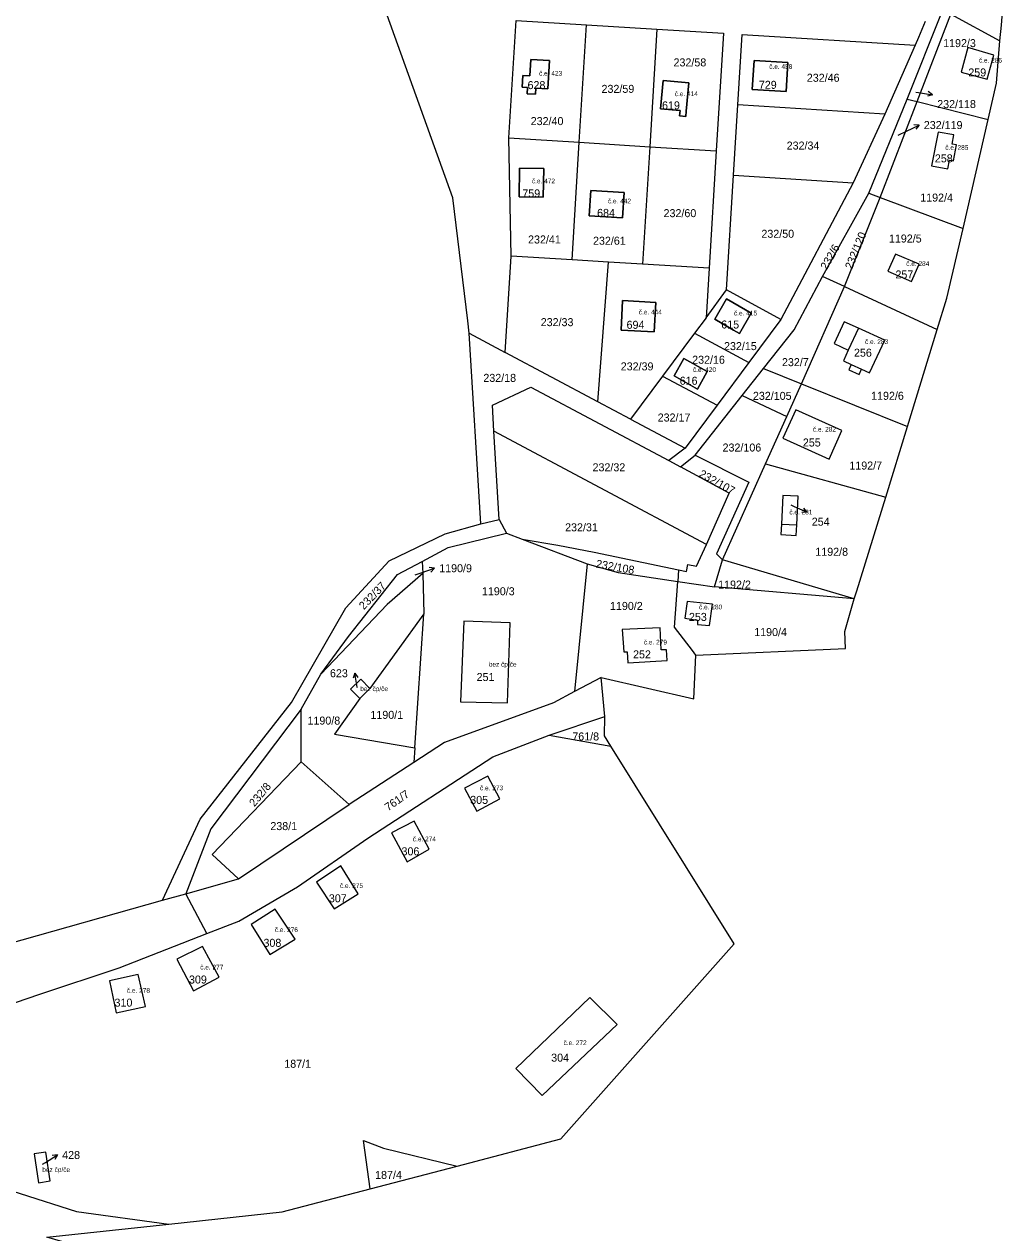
# Model space of a CAD drawing. Extents: x -887272 to -877616, y -1026687 to -1019819.
# Drawn here: x -882028.8 to -881820, y -1024011.9 to -1023755.1 of the extents above; entities that cross this region are included whole.
import ezdxf

# ---------------------------------------------------------------- set-up
doc = ezdxf.new("R2010")
doc.units = 0
for name, color, linetype in [('Definiční body', 7, 'Continuous'), ('Hranice parcel', 7, 'Continuous'), ('Parcelní čísla', 7, 'Continuous'), ('Polygon budovy', 7, 'Continuous'), ('Pop  PČ popisy', 7, 'Continuous'), ('Vnitřní kresba', 7, 'Continuous')]:
    doc.layers.add(name, color=color, linetype=linetype)

msp = doc.modelspace()

# ---------------------------------------------------------------- linework, layer by layer
at = {"layer": 'Hranice parcel'}
for p, q in [((-881841.17, -1023770.99), (-881833.85, -1023752.71)), ((-881839.01, -1023771.53), (-881831.92, -1023752.98)), ((-881831.92, -1023752.98), (-881821.47, -1023758.6)), ((-881910.86, -1023780.18), (-881909.32, -1023755.23)), ((-881909.32, -1023755.23), (-881894.37, -1023756.17)), ((-881894.37, -1023756.17), (-881895.87, -1023781.13)), ((-881839.5, -1023759.51), (-881845.94, -1023774.18)), ((-881822.15, -1023767.62), (-881821.47, -1023758.6)), ((-881823.93, -1023775.33), (-881822.15, -1023767.62)), ((-881878.07, -1023787.19), (-881877.13, -1023772.24)), ((-881845.94, -1023774.18), (-881877.13, -1023772.24)), ((-881849.34, -1023790.98), (-881841.17, -1023770.99)), ((-881846.87, -1023791.91), (-881839.01, -1023771.53)), ((-881841.17, -1023770.99), (-881839.01, -1023771.53)), ((-881839.01, -1023771.53), (-881823.93, -1023775.33)), ((-881845.94, -1023774.18), (-881852.67, -1023788.78)), ((-881829.29, -1023798.5), (-881823.93, -1023775.33)), ((-881925.34, -1023804.34), (-881925.8, -1023779.26)), ((-881925.8, -1023779.26), (-881910.86, -1023780.18)), ((-881912.34, -1023805.13), (-881910.86, -1023780.18)), ((-881910.86, -1023780.18), (-881895.87, -1023781.13)), ((-881895.87, -1023781.13), (-881897.39, -1023806.05)), ((-881895.87, -1023781.13), (-881881.74, -1023781.96)), ((-881881.74, -1023781.96), (-881883.27, -1023806.9)), ((-881879.54, -1023811.55), (-881878.07, -1023787.19)), ((-881878.07, -1023787.19), (-881852.67, -1023788.78)), ((-881852.67, -1023788.78), (-881868.03, -1023817.83)), ((-881859.13, -1023808.69), (-881849.34, -1023790.98)), ((-881854.48, -1023810.81), (-881846.87, -1023791.91)), ((-881849.34, -1023790.98), (-881846.87, -1023791.91)), ((-881846.87, -1023791.91), (-881829.29, -1023798.5)), ((-881926.61, -1023824.81), (-881925.34, -1023804.34)), ((-881912.34, -1023805.13), (-881925.34, -1023804.34)), ((-881904.6, -1023805.61), (-881912.34, -1023805.13)), ((-881906.9, -1023835.3), (-881904.6, -1023805.61)), ((-881897.39, -1023806.05), (-881904.6, -1023805.61)), ((-881883.27, -1023806.9), (-881897.39, -1023806.05)), ((-881883.27, -1023806.9), (-881883.86, -1023817.44)), ((-881854.48, -1023810.81), (-881859.13, -1023808.69)), ((-881863.64, -1023831.49), (-881854.48, -1023810.81)), ((-881854.48, -1023810.81), (-881834.76, -1023819.97)), ((-881883.86, -1023817.44), (-881879.54, -1023811.55)), ((-881868.03, -1023817.83), (-881879.54, -1023811.55)), ((-881934.25, -1023820.72), (-881934.53, -1023818.08)), ((-881883.86, -1023817.44), (-881886.36, -1023820.71)), ((-881868.03, -1023817.83), (-881874.84, -1023826.93)), ((-881854.55, -1023818.33), (-881856.7, -1023822.94)), ((-881934.25, -1023820.72), (-881926.61, -1023824.81)), ((-881931.78, -1023861.22), (-881934.25, -1023820.72)), ((-881886.36, -1023820.71), (-881893.14, -1023829.84)), ((-881886.36, -1023820.71), (-881874.84, -1023826.93)), ((-881841.09, -1023840.59), (-881834.76, -1023819.97)), ((-881906.9, -1023835.3), (-881926.61, -1023824.81)), ((-881874.84, -1023826.93), (-881881.54, -1023836.04)), ((-881876.25, -1023833.97), (-881871.67, -1023828.22)), ((-881871.67, -1023828.22), (-881863.64, -1023831.49)), ((-881853.54, -1023828.49), (-881851.38, -1023829.48)), ((-881893.14, -1023829.84), (-881899.95, -1023838.99)), ((-881893.14, -1023829.84), (-881881.54, -1023836.04)), ((-881866.75, -1023838.43), (-881863.64, -1023831.49)), ((-881863.64, -1023831.49), (-881841.09, -1023840.59)), ((-881886.24, -1023846.65), (-881876.25, -1023833.97)), ((-881876.25, -1023833.97), (-881866.75, -1023838.43)), ((-881899.95, -1023838.99), (-881906.9, -1023835.3)), ((-881881.54, -1023836.04), (-881888.36, -1023845.19)), ((-881899.95, -1023838.99), (-881888.36, -1023845.19)), ((-881871.26, -1023848.52), (-881866.75, -1023838.43)), ((-881883.83, -1023865.62), (-881928.97, -1023841.55)), ((-881927.87, -1023860.29), (-881928.97, -1023841.55)), ((-881845.7, -1023855.55), (-881841.09, -1023840.59)), ((-881888.36, -1023845.19), (-881891.81, -1023847.8)), ((-881889.34, -1023849.11), (-881886.24, -1023846.65)), ((-881891.81, -1023847.8), (-881889.34, -1023849.11)), ((-881880.38, -1023868.92), (-881871.26, -1023848.52)), ((-881871.26, -1023848.52), (-881845.7, -1023855.55)), ((-881931.78, -1023861.22), (-881927.87, -1023860.29)), ((-881927.87, -1023860.29), (-881926.28, -1023863.24)), ((-881926.28, -1023863.24), (-881922.96, -1023864.48)), ((-881922.96, -1023864.48), (-881909.13, -1023869.73)), ((-881944.19, -1023869.23), (-881944.11, -1023871.83)), ((-881909.13, -1023869.73), (-881911.84, -1023896.9)), ((-881882.08, -1023874.62), (-881880.38, -1023868.92)), ((-881852.4, -1023877.15), (-881880.38, -1023868.92)), ((-881944.11, -1023871.83), (-881943.84, -1023880.36)), ((-881889.73, -1023871.01), (-881889.91, -1023873.47)), ((-881890.59, -1023883.18), (-881889.91, -1023873.47)), ((-881889.91, -1023873.47), (-881882.08, -1023874.62)), ((-881852.4, -1023877.15), (-881882.08, -1023874.62)), ((-881943.84, -1023880.36), (-881955.32, -1023896.22)), ((-881945.8, -1023908.86), (-881943.84, -1023880.36)), ((-881969.94, -1023900.64), (-881965.77, -1023893.18)), ((-881957.46, -1023898.37), (-881955.32, -1023896.22)), ((-881906.2, -1023893.9), (-881911.84, -1023896.9)), ((-881905.4, -1023902.21), (-881906.2, -1023893.9)), ((-881969.94, -1023911.78), (-881969.94, -1023900.64)), ((-881917.21, -1023906.17), (-881905.4, -1023902.21)), ((-881917.21, -1023906.17), (-881904.1, -1023908.49)), ((-881945.8, -1023908.86), (-881946.01, -1023911.95)), ((-881959.76, -1023920.86), (-881969.94, -1023911.78)), ((-881946.01, -1023911.95), (-881959.76, -1023920.86)), ((-881983.28, -1023936.7), (-881959.76, -1023920.86)), ((-881994.47, -1023939.83), (-881983.28, -1023936.7)), ((-881999.39, -1023941.22), (-881994.47, -1023939.83)), ((-881990, -1023948.32), (-881994.47, -1023939.83)), ((-882008.61, -1023955.57), (-881990, -1023948.32)), ((-881955.28, -1024002.56), (-881936.81, -1023997.72))]:
    msp.add_line(p, q, dxfattribs=at)
for points in [[(-881821.47, -1023758.6), (-881821.15, -1023755.32), (-881819.99, -1023740.61)], [(-881934.53, -1023818.08), (-881937.73, -1023791.96), (-881953.3, -1023748.53)], [(-881925.8, -1023779.26), (-881924.27, -1023754.29), (-881909.32, -1023755.23)], [(-881837.34, -1023754.48), (-881838.77, -1023757.91), (-881839.5, -1023759.51)], [(-881894.37, -1023756.17), (-881880.22, -1023757.02), (-881881.74, -1023781.96)], [(-881877.13, -1023772.24), (-881876.21, -1023757.27), (-881839.5, -1023759.51)], [(-881824.16, -1023766.76), (-881822.73, -1023761.65), (-881828.25, -1023760.03), (-881829.66, -1023765.29), (-881824.16, -1023766.76)], [(-881917.53, -1023768.8), (-881920.1, -1023768.66), (-881920.17, -1023769.98), (-881921.91, -1023769.88), (-881921.84, -1023768.53), (-881922.95, -1023768.47), (-881922.81, -1023766), (-881921.35, -1023766.08), (-881921.16, -1023762.57), (-881917.19, -1023762.79), (-881917.53, -1023768.8)], [(-881873.71, -1023762.79), (-881866.54, -1023763.23), (-881866.86, -1023769.36), (-881874.07, -1023768.99), (-881873.71, -1023762.79)], [(-881889.51, -1023774.54), (-881889.41, -1023773.44), (-881893.58, -1023773.07), (-881893.04, -1023767.05), (-881887.57, -1023767.57), (-881888.1, -1023773.55), (-881888.2, -1023774.67), (-881889.51, -1023774.54)], [(-881836.01, -1023785.2), (-881832.51, -1023785.81), (-881832.19, -1023783.99), (-881831.29, -1023784.14), (-881830.69, -1023780.7), (-881831.59, -1023780.54), (-881831.26, -1023778.62), (-881834.61, -1023778.04), (-881836.01, -1023785.2)], [(-881923.51, -1023785.64), (-881918.39, -1023785.71), (-881918.48, -1023791.83), (-881923.59, -1023791.76), (-881923.51, -1023785.64)], [(-881908.73, -1023795.78), (-881908.39, -1023790.4), (-881901.28, -1023790.86), (-881901.62, -1023796.24), (-881908.73, -1023795.78)], [(-881834.76, -1023819.97), (-881832.71, -1023813.32), (-881829.29, -1023798.5)], [(-881840.24, -1023809.76), (-881838.63, -1023806.04), (-881843.65, -1023803.92), (-881845.24, -1023807.59), (-881840.24, -1023809.76)], [(-881871.67, -1023828.22), (-881865.19, -1023819.99), (-881859.13, -1023808.69)], [(-881901.62, -1023813.79), (-881894.55, -1023814.19), (-881894.9, -1023820.47), (-881901.97, -1023820.08), (-881901.62, -1023813.79)], [(-881876.81, -1023820.8), (-881878.09, -1023820.06), (-881882.04, -1023817.76), (-881879.53, -1023813.43), (-881875.55, -1023815.74), (-881874.3, -1023816.47), (-881876.81, -1023820.8)], [(-881851.38, -1023829.48), (-881850.87, -1023828.36), (-881849.16, -1023829.19), (-881845.94, -1023822.19), (-881851.48, -1023819.64), (-881854.55, -1023818.33)], [(-881856.7, -1023822.94), (-881853.67, -1023824.35), (-881854.7, -1023826.64), (-881853.04, -1023827.39), (-881853.54, -1023828.49)], [(-881888.59, -1023826.09), (-881883.64, -1023828.88), (-881885.74, -1023832.6), (-881890.69, -1023829.81), (-881888.59, -1023826.09)], [(-881928.97, -1023841.55), (-881929.28, -1023836), (-881921.11, -1023832.23), (-881891.81, -1023847.8)], [(-881857.76, -1023847.49), (-881855.05, -1023841.42), (-881864.81, -1023837.04), (-881867.59, -1023843.03), (-881857.76, -1023847.49)], [(-881886.24, -1023846.65), (-881874.84, -1023852.36), (-881881.66, -1023867.64), (-881880.38, -1023868.92)], [(-881883.83, -1023865.62), (-881878.98, -1023854.71), (-881889.34, -1023849.11)], [(-881867.88, -1023861.29), (-881867.99, -1023863.49), (-881864.75, -1023863.71), (-881864.63, -1023861.46), (-881864.31, -1023855.35), (-881867.56, -1023855.2), (-881867.88, -1023861.29)], [(-881852.4, -1023877.15), (-881851.84, -1023875.47), (-881845.7, -1023855.55)], [(-881999.39, -1023941.22), (-881991.4, -1023923.97), (-881972.02, -1023899.18), (-881960.42, -1023879.11), (-881951.21, -1023869.11), (-881939.33, -1023863.34), (-881931.78, -1023861.22)], [(-881944.19, -1023869.23), (-881938.67, -1023866.29), (-881926.28, -1023863.24)], [(-881922.96, -1023864.48), (-881915.42, -1023865.8), (-881907.68, -1023867.26), (-881889.73, -1023871.01)], [(-881889.73, -1023871.01), (-881888.05, -1023871.4), (-881887.75, -1023869.85), (-881885.95, -1023870.22), (-881883.83, -1023865.62)], [(-881965.77, -1023893.18), (-881959.88, -1023885.18), (-881949.43, -1023872.01), (-881944.19, -1023869.23)], [(-881909.13, -1023869.73), (-881902.57, -1023871.58), (-881889.91, -1023873.47)], [(-881944.11, -1023871.83), (-881951.66, -1023878.36), (-881965.77, -1023893.18)], [(-881882.54, -1023878.28), (-881887.94, -1023877.78), (-881888.42, -1023881.32), (-881885.75, -1023881.68), (-881885.7, -1023882.64), (-881883.16, -1023882.84), (-881882.54, -1023878.28)], [(-881886.09, -1023889.14), (-881854.28, -1023887.76), (-881854.42, -1023884.14), (-881852.4, -1023877.15)], [(-881935.37, -1023881.94), (-881936.05, -1023899.09), (-881926.11, -1023899.29), (-881925.52, -1023882.28), (-881935.37, -1023881.94)], [(-881900.5, -1023890.77), (-881892.17, -1023890.25), (-881892.27, -1023888), (-881893.42, -1023888.05), (-881893.63, -1023883.36), (-881901.72, -1023883.72), (-881901.39, -1023888.47), (-881900.65, -1023888.42), (-881900.5, -1023890.77)], [(-881886.09, -1023889.14), (-881886.81, -1023888.19), (-881890.59, -1023883.18)], [(-881906.2, -1023893.9), (-881886.52, -1023898.46), (-881886.09, -1023889.14)], [(-881955.32, -1023896.22), (-881957.25, -1023894.23), (-881959.47, -1023896.38), (-881957.46, -1023898.37)], [(-881957.46, -1023898.37), (-881962.85, -1023905.91), (-881945.8, -1023908.86)], [(-881911.84, -1023896.9), (-881916.32, -1023899.28), (-881939.46, -1023907.7), (-881946.01, -1023911.95)], [(-881969.94, -1023900.64), (-881989.12, -1023926.07), (-881994.47, -1023939.83)], [(-881904.1, -1023908.49), (-881905.47, -1023906.29), (-881905.4, -1023902.21)], [(-881955.79, -1023928.05), (-881929.24, -1023910.73), (-881917.21, -1023906.17)], [(-881936.81, -1023997.72), (-881914.78, -1023991.95), (-881877.9, -1023950.5), (-881904.1, -1023908.49)], [(-881983.28, -1023936.7), (-881988.84, -1023931.52), (-881969.94, -1023911.78)], [(-881935.2, -1023917.4), (-881932.6, -1023922.28), (-881927.73, -1023919.68), (-881930.26, -1023914.84), (-881935.2, -1023917.4)], [(-881942.7, -1023930.38), (-881945.94, -1023924.4), (-881950.74, -1023926.92), (-881947.42, -1023933.04), (-881942.7, -1023930.38)], [(-881990, -1023948.32), (-881983.19, -1023945.67), (-881970.68, -1023938.4), (-881955.79, -1023928.05)], [(-881961.52, -1023933.92), (-881966.68, -1023937.36), (-881962.94, -1023943.08), (-881957.8, -1023939.88), (-881961.52, -1023933.92)], [(-882056.31, -1023959.06), (-882032.46, -1023950.59), (-881999.39, -1023941.22)], [(-881971.2, -1023949.5), (-881975.48, -1023943.14), (-881980.56, -1023946.36), (-881976.56, -1023952.78), (-881971.2, -1023949.5)], [(-881992.82, -1023960.5), (-881987.35, -1023957.56), (-881990.9, -1023951.02), (-881996.34, -1023953.74), (-881992.82, -1023960.5)], [(-882101.11, -1023991.13), (-882086.42, -1023982.08), (-882025.64, -1023961.24), (-882008.61, -1023955.57)], [(-882003.04, -1023963.78), (-882004.58, -1023957.02), (-882010.68, -1023958.32), (-882009.24, -1023965.13), (-882003.04, -1023963.78)], [(-881918.72, -1023982.68), (-881902.8, -1023967.62), (-881908.62, -1023961.86), (-881924.32, -1023977), (-881918.72, -1023982.68)], [(-881955.28, -1024002.56), (-881956.69, -1023992.3), (-881952.41, -1023993.93), (-881936.81, -1023997.72)], [(-882123.98, -1024005.14), (-882077.02, -1023996.18), (-882041.7, -1023999.68), (-882017.67, -1024007.34), (-881998.04, -1024010.02)], [(-882023.24, -1024000.83), (-882024.16, -1023994.74), (-882026.7, -1023995.08), (-882025.74, -1024001.24), (-882023.24, -1024000.83)], [(-881998.04, -1024010.02), (-881973.98, -1024007.46), (-881955.28, -1024002.56)], [(-881996.26, -1024020.9), (-882024.01, -1024012.79), (-881998.04, -1024010.02)]]:
    msp.add_lwpolyline(points, dxfattribs=at)
at = {"layer": 'Polygon budovy'}
for points in [[(-881829.66, -1023765.29), (-881824.16, -1023766.76), (-881822.73, -1023761.65), (-881828.25, -1023760.03)], [(-881921.16, -1023762.57), (-881921.35, -1023766.08), (-881922.81, -1023766), (-881922.95, -1023768.47), (-881921.84, -1023768.53), (-881921.91, -1023769.88), (-881920.17, -1023769.98), (-881920.1, -1023768.66), (-881917.53, -1023768.8), (-881917.19, -1023762.79)], [(-881873.71, -1023762.79), (-881874.07, -1023768.99), (-881866.86, -1023769.36), (-881866.54, -1023763.23)], [(-881893.04, -1023767.05), (-881893.58, -1023773.07), (-881889.41, -1023773.44), (-881889.51, -1023774.54), (-881888.2, -1023774.67), (-881888.1, -1023773.55), (-881887.57, -1023767.57)], [(-881836.01, -1023785.2), (-881832.51, -1023785.81), (-881832.19, -1023783.99), (-881831.29, -1023784.14), (-881830.69, -1023780.7), (-881831.59, -1023780.54), (-881831.26, -1023778.62), (-881834.61, -1023778.04)], [(-881923.59, -1023791.76), (-881918.48, -1023791.83), (-881918.39, -1023785.71), (-881923.51, -1023785.64)], [(-881908.39, -1023790.4), (-881908.73, -1023795.78), (-881901.62, -1023796.24), (-881901.28, -1023790.86)], [(-881843.65, -1023803.92), (-881845.24, -1023807.59), (-881840.24, -1023809.76), (-881838.63, -1023806.04)], [(-881901.62, -1023813.79), (-881901.97, -1023820.08), (-881894.9, -1023820.47), (-881894.55, -1023814.19)], [(-881879.53, -1023813.43), (-881882.04, -1023817.76), (-881878.09, -1023820.06), (-881876.81, -1023820.8), (-881874.3, -1023816.47), (-881875.55, -1023815.74)], [(-881845.94, -1023822.19), (-881851.48, -1023819.64), (-881853.67, -1023824.35), (-881854.7, -1023826.64), (-881853.04, -1023827.39), (-881850.87, -1023828.36), (-881849.16, -1023829.19)], [(-881890.69, -1023829.81), (-881885.74, -1023832.6), (-881883.64, -1023828.88), (-881888.59, -1023826.09)], [(-881867.59, -1023843.03), (-881857.76, -1023847.49), (-881855.05, -1023841.42), (-881864.81, -1023837.04)], [(-881867.56, -1023855.2), (-881867.88, -1023861.29), (-881864.63, -1023861.46), (-881864.31, -1023855.35)], [(-881887.94, -1023877.78), (-881888.42, -1023881.32), (-881885.75, -1023881.68), (-881885.7, -1023882.64), (-881883.16, -1023882.84), (-881882.54, -1023878.28)], [(-881935.37, -1023881.94), (-881936.05, -1023899.09), (-881926.11, -1023899.29), (-881925.52, -1023882.28)], [(-881901.72, -1023883.72), (-881901.39, -1023888.47), (-881900.65, -1023888.42), (-881900.5, -1023890.77), (-881892.17, -1023890.25), (-881892.27, -1023888), (-881893.42, -1023888.05), (-881893.63, -1023883.36)], [(-881955.32, -1023896.22), (-881957.25, -1023894.23), (-881959.47, -1023896.38), (-881957.46, -1023898.37)], [(-881930.26, -1023914.84), (-881935.2, -1023917.4), (-881932.6, -1023922.28), (-881927.73, -1023919.68)], [(-881950.74, -1023926.92), (-881947.42, -1023933.04), (-881942.7, -1023930.38), (-881945.94, -1023924.4)], [(-881966.68, -1023937.36), (-881962.94, -1023943.08), (-881957.8, -1023939.88), (-881961.52, -1023933.92)], [(-881976.56, -1023952.78), (-881971.2, -1023949.5), (-881975.48, -1023943.14), (-881980.56, -1023946.36)], [(-881987.35, -1023957.56), (-881990.9, -1023951.02), (-881996.34, -1023953.74), (-881992.82, -1023960.5)], [(-882004.58, -1023957.02), (-882010.68, -1023958.32), (-882009.24, -1023965.13), (-882003.04, -1023963.78)], [(-881924.32, -1023977), (-881918.72, -1023982.68), (-881902.8, -1023967.62), (-881908.62, -1023961.86)], [(-882026.7, -1023995.08), (-882025.74, -1024001.24), (-882023.24, -1024000.83), (-882024.16, -1023994.74)]]:
    msp.add_lwpolyline(points, close=True, dxfattribs=at)
at = {"layer": 'Pop  PČ popisy'}
for p, q in [((-881839.33, -1023769.5), (-881838.74, -1023769.59)), ((-881838.74, -1023769.59), (-881835.78, -1023770.06)), ((-881835.78, -1023770.06), (-881836.84, -1023770.4)), ((-881835.78, -1023770.06), (-881836.69, -1023769.41)), ((-881843.07, -1023778.67), (-881841.33, -1023777.82)), ((-881841.33, -1023777.82), (-881838.63, -1023776.5)), ((-881838.63, -1023776.5), (-881839.75, -1023776.49)), ((-881838.63, -1023776.5), (-881839.31, -1023777.39)), ((-881865.91, -1023857.23), (-881865.18, -1023857.56)), ((-881865.18, -1023857.56), (-881862.44, -1023858.78)), ((-881862.44, -1023858.78), (-881863.56, -1023858.83)), ((-881862.44, -1023858.78), (-881863.15, -1023857.92)), ((-881941.59, -1023870.69), (-881942.7, -1023870.55)), ((-881945.68, -1023872.1), (-881944.43, -1023871.67)), ((-881944.43, -1023871.67), (-881941.59, -1023870.69)), ((-881941.59, -1023870.69), (-881942.38, -1023871.49)), ((-881958.54, -1023892.98), (-881958.86, -1023894.06)), ((-881958.02, -1023895.94), (-881958.54, -1023892.98)), ((-881958.54, -1023892.98), (-881957.87, -1023893.88)), ((-881957.99, -1023896.11), (-881958.02, -1023895.94)), ((-882024.26, -1023996.93), (-882021.71, -1023995.34)), ((-882021.71, -1023995.34), (-882022.83, -1023995.45)), ((-882021.71, -1023995.34), (-882022.3, -1023996.3)), ((-882024.91, -1023997.33), (-882024.26, -1023996.93))]:
    msp.add_line(p, q, dxfattribs=at)
at = {"layer": 'Vnitřní kresba'}
for p, q in [((-881851.48, -1023819.64), (-881853.67, -1023824.35)), ((-881853.04, -1023827.39), (-881850.87, -1023828.36)), ((-881867.88, -1023861.29), (-881864.63, -1023861.46))]:
    msp.add_line(p, q, dxfattribs=at)

# ---------------------------------------------------------------- texts
at = {"layer": 'Definiční body'}
for s, p in [('č.e. 286', (-881825.93, -1023763.24)), ('č.e. 423', (-881919.38, -1023766.01)), ('č.e. 458', (-881870.48, -1023764.57)), ('č.e. 414', (-881890.55, -1023770.37)), ('č.e. 285', (-881833.07, -1023781.77)), ('č.e. 472', (-881920.91, -1023788.89)), ('č.e. 442', (-881904.75, -1023793.15)), ('č.e. 284', (-881841.37, -1023806.45)), ('č.e. 444', (-881898.19, -1023816.74)), ('č.e. 415', (-881877.97, -1023816.97)), ('č.e. 283', (-881850.12, -1023823.04)), ('č.e. 420', (-881886.69, -1023828.96)), ('č.e. 282', (-881861.21, -1023841.65)), ('č.e. 281', (-881866.21, -1023859.25)), ('č.e. 280', (-881885.39, -1023879.41)), ('č.e. 279', (-881897.12, -1023886.88)), ('bez čp/če', (-881930.06, -1023891.59)), ('bez čp/če', (-881957.38, -1023896.79)), ('č.e. 273', (-881931.93, -1023917.86)), ('č.e. 274', (-881946.21, -1023928.7)), ('č.e. 275', (-881961.69, -1023938.62)), ('č.e. 276', (-881975.54, -1023947.99)), ('č.e. 277', (-881991.38, -1023955.94)), ('č.e. 278', (-882006.97, -1023960.88)), ('č.e. 272', (-881914.18, -1023972)), ('bez čp/če', (-882024.94, -1023998.97))]:
    msp.add_text(s, height=1, dxfattribs=at).set_placement(p)
at = {"layer": 'Parcelní čísla'}
for s, p in [('1192/3', (-881833.52, -1023759.95)), ('232/58', (-881890.81, -1023764.05)), ('259', (-881828.17, -1023766.18)), ('628', (-881921.83, -1023768.87)), ('729', (-881872.68, -1023768.81)), ('232/46', (-881862.49, -1023767.31)), ('232/59', (-881906.11, -1023769.67)), ('619', (-881893.25, -1023773.18)), ('232/118', (-881834.78, -1023772.9)), ('232/40', (-881921.16, -1023776.52)), ('232/119', (-881837.63, -1023777.36)), ('232/34', (-881866.77, -1023781.72)), ('258', (-881835.28, -1023784.44)), ('759', (-881922.94, -1023791.88)), ('1192/4', (-881838.39, -1023792.77)), ('684', (-881907.05, -1023796.03)), ('232/60', (-881892.93, -1023796.08)), ('232/41', (-881921.72, -1023801.67)), ('232/61', (-881907.92, -1023801.94)), ('232/50', (-881872.14, -1023800.46)), ('1192/5', (-881845.04, -1023801.47)), ('257', (-881843.66, -1023809.11)), ('232/33', (-881919.03, -1023819.24)), ('694', (-881900.79, -1023819.8)), ('615', (-881880.67, -1023819.74)), ('232/15', (-881880.08, -1023824.33)), ('256', (-881852.47, -1023825.73)), ('232/39', (-881902.03, -1023828.64)), ('232/16', (-881886.85, -1023827.23)), ('232/7', (-881867.77, -1023827.74)), ('232/18', (-881931.22, -1023831.08)), ('616', (-881889.5, -1023831.69)), ('232/105', (-881873.94, -1023834.9)), ('1192/6', (-881848.83, -1023834.89)), ('232/17', (-881894.18, -1023839.5)), ('232/106', (-881880.39, -1023845.88)), ('255', (-881863.33, -1023844.81)), ('232/32', (-881908.02, -1023850.08)), ('1192/7', (-881853.45, -1023849.71)), ('254', (-881861.44, -1023861.64)), ('232/31', (-881913.85, -1023862.83)), ('1192/8', (-881860.68, -1023868.03)), ('1190/9', (-881940.6, -1023871.53)), ('1190/3', (-881931.52, -1023876.42)), ('1192/2', (-881881.33, -1023875)), ('1190/2', (-881904.31, -1023879.54)), ('253', (-881887.54, -1023881.87)), ('1190/4', (-881873.67, -1023885.09)), ('252', (-881899.41, -1023889.83)), ('623', (-881963.81, -1023893.84)), ('251', (-881932.66, -1023894.64)), ('1190/1', (-881955.22, -1023902.68)), ('1190/8', (-881968.59, -1023903.9)), ('761/8', (-881912.32, -1023907.27)), ('305', (-881934.01, -1023920.75)), ('238/1', (-881976.48, -1023926.32)), ('306', (-881948.61, -1023931.68)), ('307', (-881964.05, -1023941.66)), ('308', (-881977.94, -1023951.12)), ('309', (-881993.77, -1023958.92)), ('310', (-882009.59, -1023963.83)), ('187/1', (-881973.52, -1023976.82)), ('304', (-881916.81, -1023975.52)), ('428', (-882020.71, -1023996.21)), ('187/4', (-881954.22, -1024000.44))]:
    msp.add_text(s, height=1.7, dxfattribs=at).set_placement(p)
for s, rotation, p in [('232/120', 68, (-881852.88, -1023807.29)), ('232/6', 60, (-881858.25, -1023807.4)), ('232/107', 331, (-881885.55, -1023851.13)), ('232/108', 350, (-881907.39, -1023870.51)), ('232/37', 46, (-881956.61, -1023879.6)), ('232/8', 50, (-881979.86, -1023921.46)), ('761/7', 35, (-881951.44, -1023922.35))]:
    msp.add_text(s, height=1.7, rotation=rotation, dxfattribs=at).set_placement(p)

doc.saveas('drawing.dxf')
